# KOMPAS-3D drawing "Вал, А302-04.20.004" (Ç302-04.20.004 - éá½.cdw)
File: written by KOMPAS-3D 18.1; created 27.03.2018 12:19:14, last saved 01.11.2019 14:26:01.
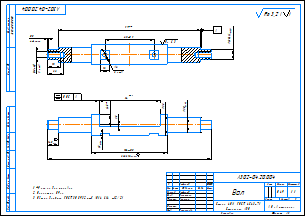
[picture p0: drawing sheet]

Sheet 1: A3, landscape

Document properties: Автор: Милов; Параметр неуказанной шероховатости: Ra 3,2; Полное имя файла: ..\3Д\А302-00.20.004 - Вал.m3d; Масса: 0.49487; Организация: Милов

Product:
- Part/product: Вал  | designation А302-04.20.004
    Материал: Сталь 40Х  ГОСТ 4543-71 (density 7825 kg/m3)
    Масса: 0.49487
    Раздел спецификации: Детали
    Форматы листов документа: A3
    source file: ..\Чертежи ПВХ\А302-03.20.004 - Вал.cdw, А302-04.20.004 - Вал.cdw
- Part/product: Вал  | designation А302-02.20.004
    Материал: Сталь 40Х  ГОСТ 4543-71 (density 7825 kg/m3)
    Масса: 0.365977
    Раздел спецификации: Детали
    Форматы листов документа: A3
    source file: ..\Чертежи ПВХ\А302-02.20.004 - Вал.cdw
- Part/product: Вал  | designation А302-00.20.004
    Материал: Сталь 40Х  ГОСТ 4543-71 (density 7825 kg/m3)
    Масса: 0.363087
    Раздел спецификации: Детали
    Форматы листов документа: A3

Title block, sheet 1: Наименование: Вал; designation: А302-04.20.004; Материал: Сталь 40Х  ГОСТ 4543-71 / Стержень  30; Масса: 0,49; scale: 1:1; Количество листов документа: 1; organisation: АО «Астерион»; Форматы листов документа: A3; stored path: Z:\Мембранные насосы\Мембранный электропривод\А302-00.00.000 - ASTRA-302 (МЭ200)\Чертежи\А302-00.20.004 - Вал.cdw; Разработал: Лифлянд; Проверил: Борисенко; Т. контр.: Лучихин; Утвердил: Григорьева

Views: Вид 1, Спереди, Проекционный вид 2, Местный разрез 1, Местный разрез 2
Referenced files in Z:\Мембранные насосы\Мембранный электропривод\А302-00.00.000 - ASTRA-302 (МЭ200)\3Д\: А302-00.20.004 - Вал.m3d
Referenced files in D:\Мембранные насосы\Мембранный электропривод\А302-00.00.000 - ASTRA-302 (МЭ200)\3Д\: А302-00.20.004 - Вал.m3d
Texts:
  Ra 6,3
  Ra 3,2
  Ra 3,2 ( )
Dimensions and other numbers on the sheet: 226; 84; 0,05; 20; 2,5; 16,5; 28; 104±0,5; 1,5; 14,5; 68±0,1; 6; 2 отв.; -6Н; 8; 0,5; 4 фаски; 18; 22; 197; 13,5; 12; 1; 1:1; 0,49; 01.11.2019

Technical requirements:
  *Размер для справок.
  Покрытие: Ц9хр.
  Общие допуски ГОСТ 30893.2-mK (H14, h14,  t2/2).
